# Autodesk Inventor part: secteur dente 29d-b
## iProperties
Author: chr
Shininess: 20.0
Angle Display Precision: 2
Document Length Units: 11269
Document Angle Units: 11283
Document Time Units: 11279
Document Mass Units: 11290
Document Length Units Precision: 3
Document Angle Units Precision: 2
Compacted: False
PropertySet Name: _Private Model Information
Created: 2002-03
Part Number: secteur dente 29d-b
Material: Par défaut
Document SubType Name: Modélisation
Designer: chr
Control State: 0
Master: False
Checked Out: False
PropertySet Name: Design Tracking Control
Density: 0.0
Volumn: 0.0
Area: 0.0
PropertySet Name: Model Information
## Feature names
1. Base1
2. Extrusion1
3. Extrusion2
4. Réseau circulaire1 [Circular Pattern]
